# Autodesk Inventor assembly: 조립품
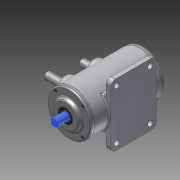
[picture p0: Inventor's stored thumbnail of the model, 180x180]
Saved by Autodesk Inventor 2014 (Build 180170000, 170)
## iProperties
Created: 2014-12
Part Number: 조립품
Document SubType Name: Assembly
Designer: Owner
Author: Owner
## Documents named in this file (10)
- C:\Users\Owner\Desktop\441223V1015\답안조립품.iam
- C:\Users\Owner\Desktop\441223V1015\M4-소켓머리.ipt
- C:\Users\Owner\Desktop\441223V1015\뒷커버.ipt
- C:\Users\Owner\Desktop\441223V1015\베어링 6203.ipt
- C:\Users\Owner\Desktop\441223V1015\본체.ipt
- C:\Users\Owner\Desktop\441223V1015\부시.ipt
- C:\Users\Owner\Desktop\441223V1015\슬라이더.ipt
- C:\Users\Owner\Desktop\441223V1015\앞커버.ipt
- C:\Users\Owner\Desktop\441223V1015\오일실.ipt
- C:\Users\Owner\Desktop\441223V1015\축.ipt
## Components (11 placed, 3 different names)
1. 7-베어링 6203:1
2. 8-오일실:1
3. 7-베어링 6203:2
4. 9-M4-소켓머리:1
5. 9-M4-소켓머리:3
6. 9-M4-소켓머리:4
7. 9-M4-소켓머리:5
8. 9-M4-소켓머리:2
9. 9-M4-소켓머리:6
10. 9-M4-소켓머리:7
11. 9-M4-소켓머리:8
